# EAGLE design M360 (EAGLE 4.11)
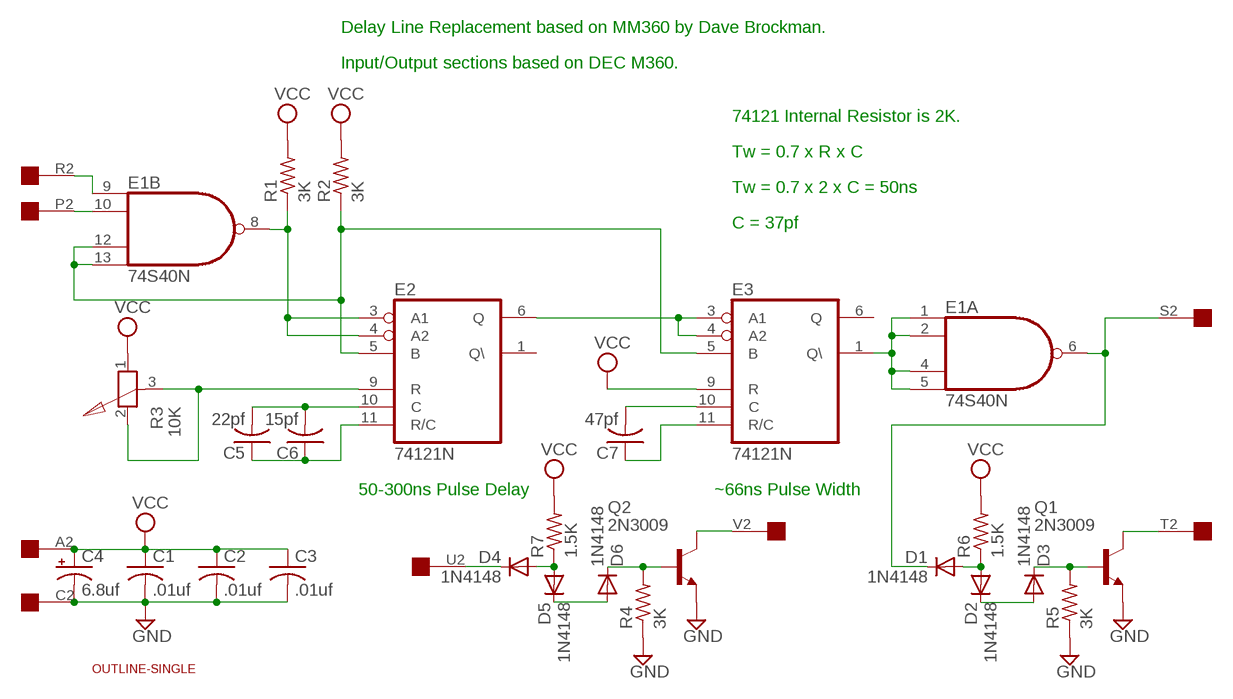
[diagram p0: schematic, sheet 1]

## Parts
C1  .01uf  C-US050-025X075  [C050-025X075]
C2  .01uf  C-US050-025X075  [C050-025X075]
C3  .01uf  C-US050-025X075  [C050-025X075]
C4  6.8uf  CPOL-USE15-5AXIAL  [E15-5]
C5  22pf  C-US050-025X075  [C050-025X075]
C6  15pf  C-US050-025X075  [C050-025X075]
C7  47pf  C-US050-025X075  [C050-025X075]
D1  1N4148  [DO35-10]
D2  1N4148  [DO35-10]
D3  1N4148  [DO35-10]
D4  1N4148  [DO35-10]
D5  1N4148  [DO35-10]
D6  1N4148  [DO35-10]
E1  74S40N  74S20N  [DIL14]
E2  74121N  [DIL14]
E3  74121N  [DIL14]
Q1  2N3009  2N2405  [TO5]
Q2  2N3009  2N2405  [TO5]
R1  3K  R-US_0207/10  [0207/10]
R2  3K  R-US_0207/10  [0207/10]
R3  10K  POT-TRIM  [PT-SPIN]
R4  3K  R-US_0207/10  [0207/10]
R5  3K  R-US_0207/10  [0207/10]
R6  1.5K  R-US_0207/10  [0207/10]
R7  1.5K  R-US_0207/10  [0207/10]
U$1  OUTLINE-SINGLE  [SINGLE]
U$3  EDGE-1  [EDGE-CON1]

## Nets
GND [supply]: C1.2 C2.2 C3.2 C4.- Q1.1(E) Q2.1(E) R4.1 R5.1 U$3.C2
N$1: E2.6(Q) E3.3(A1) E3.4(A2)
N$2: E1.8(B:O) E2.3(A1) E2.4(A2) R1.1
N$3: E1.12(B:I2) E1.13(B:I3) E2.5(B) E3.5(B) R2.1
N$4: E1.1(A:I0) E1.2(A:I1) E1.4(A:I2) E1.5(A:I3) E3.1(Q\)
N$5: E1.10(B:I1) U$3.P2
N$6: E1.9(B:I0) U$3.R2
N$7: C5.2 C6.2 E2.10(C)
N$8: C7.2 E3.10(C)
N$9: C5.1 C6.1 E2.11(R/C)
N$10: E2.9(R) R3.2 R3.3
N$11: D1.C E1.6(A:O) U$3.S2
N$12: Q2.3(C) U$3.V2
N$13: Q1.3(C) U$3.T2
N$14: D4.C U$3.U2
N$15: D6.C Q2.2(B) R4.2
N$16: C7.1 E3.11(R/C)
N$17: D5.C D6.A
N$18: D4.A D5.A R7.1
N$19: D1.A D2.A R6.1
N$20: D2.C D3.A
N$21: D3.C Q1.2(B) R5.2
VCC [supply]: C1.1 C2.1 C3.1 C4.+ E3.9(R) R1.2 R2.2 R3.1 R6.2 R7.2 U$3.A2
Unconnected: E2.1(Q\) E3.6(Q) U$3.B2 U$3.D2 U$3.E2 U$3.F2 U$3.H2 U$3.J2 U$3.K2 U$3.L2 U$3.M2 U$3.N2

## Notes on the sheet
- Delay Line Replacement based on MM360 by Dave Brockman.
- Input/Output sections based on DEC M360.
- 74121 Internal Resistor is 2K.
- Tw = 0.7 x R x C
- Tw = 0.7 x 2 x C = 50ns
- C = 37pf
- 50-300ns Pulse Delay | ~66ns Pulse Width

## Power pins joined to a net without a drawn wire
GND: E1.7(P:GND) E2.7(GND) E3.7(GND)
VCC: E1.14(P:VCC) E2.14(VCC) E3.14(VCC)

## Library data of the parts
C1-C3 C5-C7 = rcl:C-US: CAPACITOR, American symbol
C4 = rcl:CPOL-US: POLARIZED CAPACITOR, American symbol
D1-D6 = diode:1N4148: DIODE
E1 = 74xx-us:74*20: Dual 4-input NAND gate
E2 E3 = 74xx-jameco:74*121: Monostable MULTIVIBRATOR, schmitt trigger inputs
Q1 Q2 = transistor:2N2405: NPN TRANSISTOR
R1 R2 R4-R7 = rcl:R-US_: RESISTOR, American symbol
R3 = discrete:POT-TRIM
U$1 = dec-con:OUTLINE-*: Board outlines for DEC boards.
U$3 = dec-con:EDGE-1: Single-Sided DEC Edge Connector -- (side 2)

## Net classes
1 supply: width 0.762 mm, drill 0.508 mm

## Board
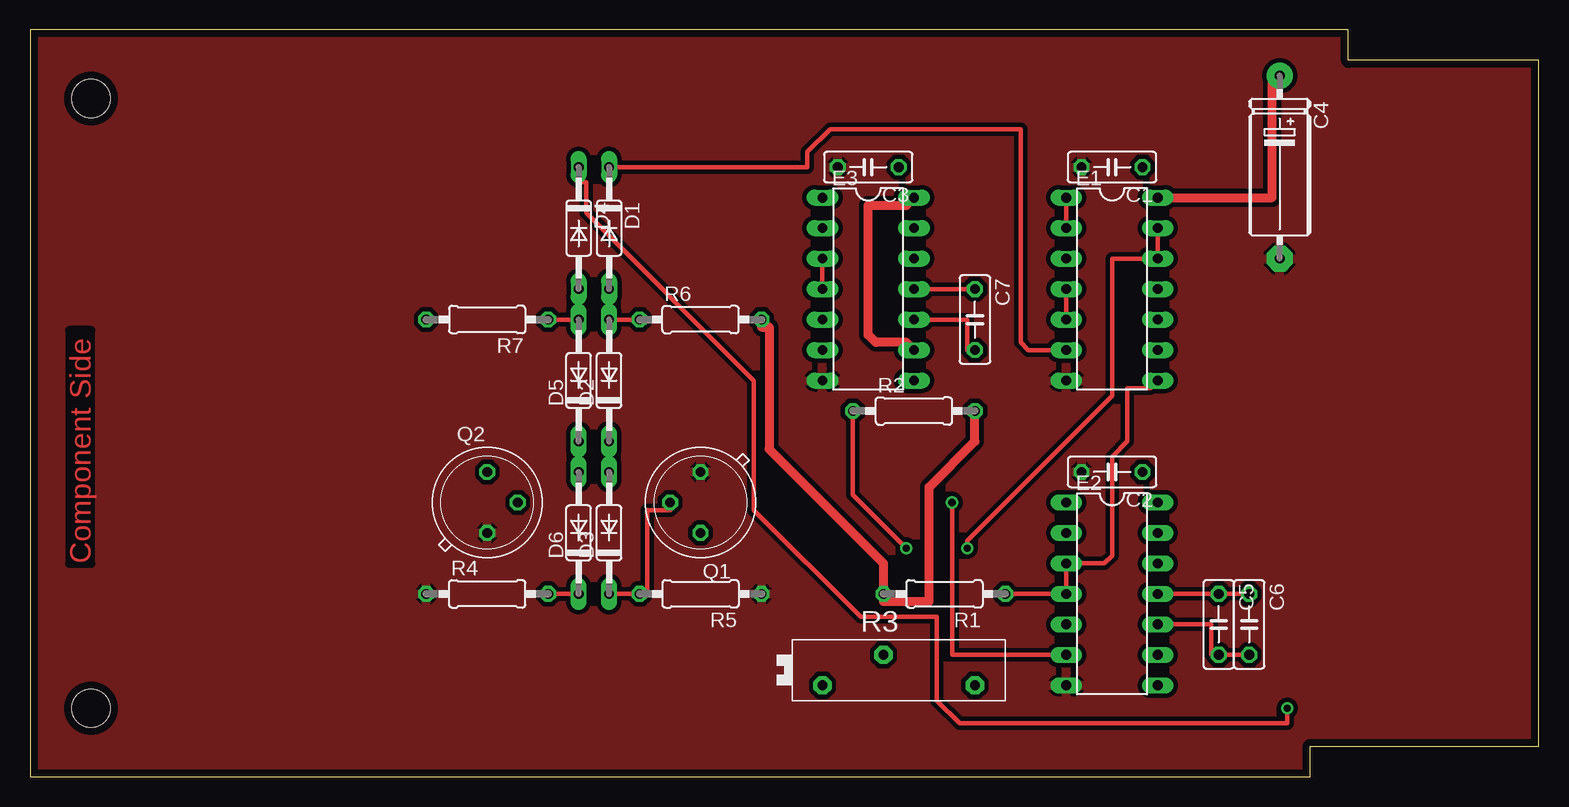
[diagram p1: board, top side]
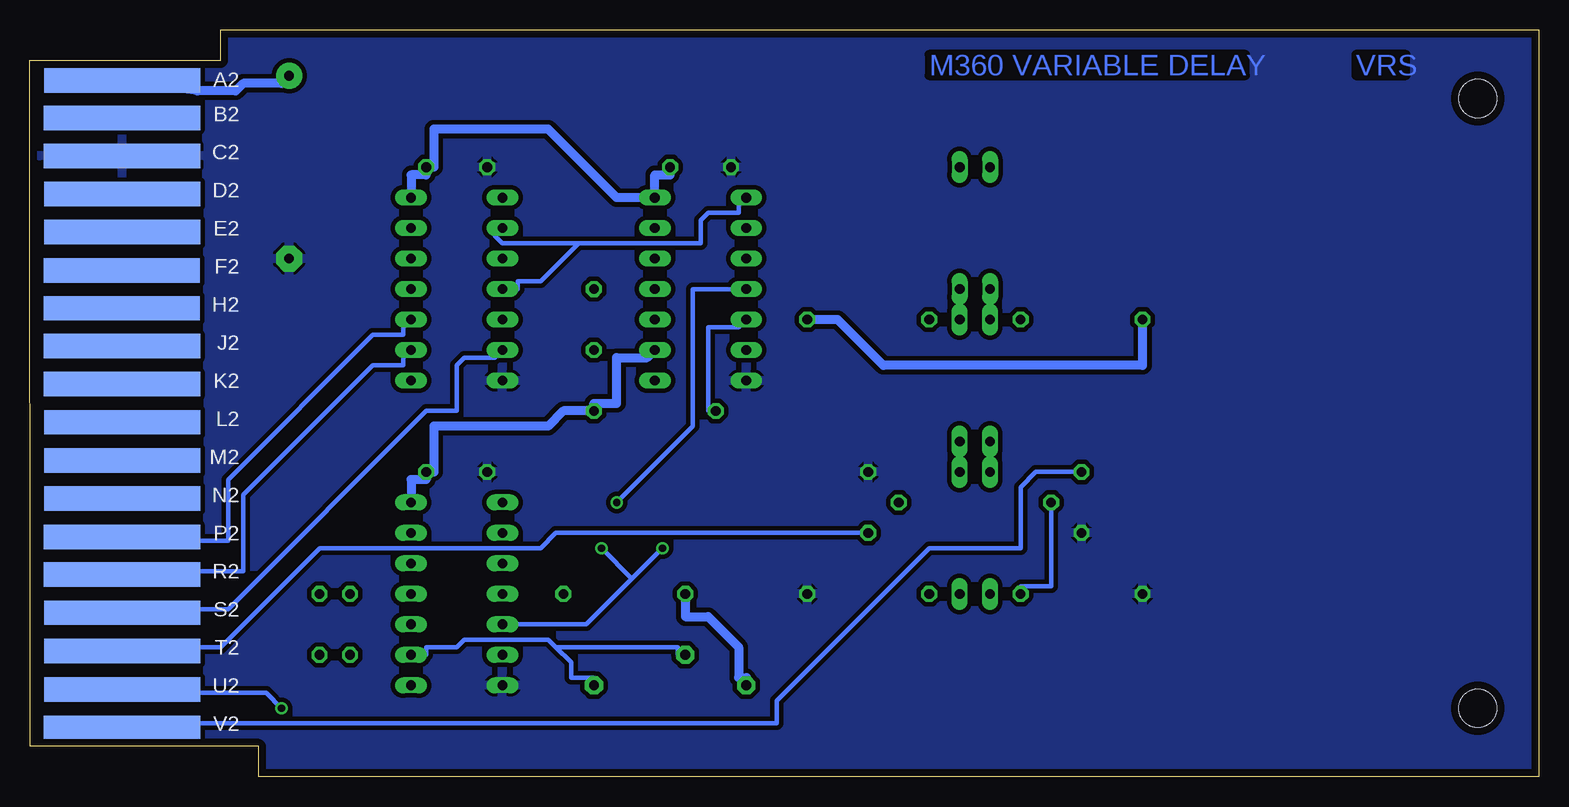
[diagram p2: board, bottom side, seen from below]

Size 125.73 x 62.23 mm. Coordinates in mm from the lower left corner, seen from the top.
Copper layers (1*16): Top 0.035mm / dielectric 1.5mm / Bottom 0.035mm
Design rules "15mils": minimum track width 15mil, minimum drill 24mil, track to track 15mil, track to pad 10mil, pad to pad 10mil, via to via 10mil, smd to smd 10mil, copper to edge 25mil, drill to drill 10mil, minimum pad ring 10mil, minimum via ring 8mil, stop-mask expansion 0mil, vias tented up to drill 0mil, thermal gap 10mil

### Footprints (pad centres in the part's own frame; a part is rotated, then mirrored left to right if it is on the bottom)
C050-025X075 = drill 0.813 octagon: 1 -2.54,0; 2 2.54,0
E15-5 = drill 0.813 pad 2.159 round: + -7.62,0 | drill 0.813 pad 2.159 octagon: - 7.62,0
DO35-10 = drill 0.813 long: A 5.08,0; C -5.08,0
DIL14 = drill 0.813 long: 1 -7.62,-3.81; 2 -5.08,-3.81; 3 -2.54,-3.81; 4 0,-3.81; 5 2.54,-3.81; 6 5.08,-3.81; 7 7.62,-3.81; 8 7.62,3.81; 9 5.08,3.81; 10 2.54,3.81; 11 0,3.81; 12 -2.54,3.81; 13 -5.08,3.81; 14 -7.62,3.81
TO5 = drill 0.813 octagon: 1 0,-2.54; 2 2.54,0; 3 0,2.54
0207/10 = drill 0.813 octagon: 1 -5.08,0; 2 5.08,0
PT-SPIN = drill 0.813 pad 1.524 octagon: 1 -6.35,-1.27; 2 6.35,-1.27; 3 -1.27,1.27
SINGLE = hole 3.175: 120.65,56.515; 120.65,5.715
EDGE-CON1 = smd 13.017 x 2.032 bottom: A2 7.69,4.194; B2 7.668,7.328; C2 7.668,10.49; D2 7.693,13.665; E2 7.693,16.84; F2 7.642,20.041; H2 7.642,23.19; J2 7.668,26.34; K2 7.668,29.515; L2 7.693,32.69; M2 7.693,35.89; N2 7.693,39.04; P2 7.668,42.24; R2 7.668,45.39; S2 7.693,48.565; T2 7.693,51.74; U2 7.693,54.966 | smd 13.017 x 1.905 bottom: V2 7.668,58.102

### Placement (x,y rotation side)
C1  90.17,50.8 180 top
C2  90.17,25.4 180 top
C3  69.85,50.8 180 top
C4  104.14,50.8 270 top
C5  99.06,12.7 270 top
C6  101.6,12.7 270 top
C7  78.74,38.1 270 top
D1  48.26,45.72 270 top
D2  48.26,33.02 90 top
D3  48.26,20.32 90 top
D4  45.72,45.72 270 top
D5  45.72,33.02 90 top
D6  45.72,20.32 90 top
E1  90.17,40.64 270 top
E2  90.17,15.24 270 top
E3  69.85,40.64 270 top
Q1  55.88,22.86 180 top
Q2  38.1,22.86 0 top
R1  76.2,15.24 180 top
R2  73.66,30.48 0 top
R3  72.39,8.89 0 top
R4  38.1,15.24 0 top
R5  55.88,15.24 180 top
R6  55.88,38.1 0 top
R7  38.1,38.1 180 top
U$1  125.73,62.23 180 top
U$3  125.73,62.23 180 top

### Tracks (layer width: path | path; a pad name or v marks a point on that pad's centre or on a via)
GND
  pour Bottom: 0,0 125.73,0 125.73,62.23 0,62.23
  pour Top: 0,0 125.73,0 125.73,62.23 0,62.23
N$1  (via drill 0.61)
  Top 0.381: E3.4 E3.3 | v76.83,22.86 76.83,10.16 E2.6
  Bottom 0.381: v76.83,22.86 70.48,29.21 70.48,40.64 E3.4
N$2
  Top 0.381: R1.1 E2.4 E2.3 89.53,17.78 90.17,18.41 90.17,26.67 91.44,27.94 91.44,32.38 93.34,32.38 E1.8
N$3  (via drill 0.61)
  Top 0.381: E1.13 E1.12 90.17,43.18 90.17,31.75 78.11,19.68 v78.11,19.05 | v73.03,19.05 68.58,23.5 R2.1
  Bottom 0.381: R2.1 69.22,30.48 69.22,37.47 66.67,37.47 E3.5 | v73.03,19.05 75.56,16.51 | 75.56,16.51 79.38,12.7 E2.5 | 75.56,16.51 v78.11,19.05
N$4
  Top 0.381: E1.4 E1.5 | E1.2 E1.1
  Bottom 0.381: 80.01,44.45 86.36,44.45 87,45.09 E1.2 | 80.01,44.45 69.85,44.45 69.85,46.35 69.22,46.99 66.67,46.99 66.67,47.62 E3.1 | 80.01,44.45 83.19,41.27 85.09,41.27 85.09,40.64 E1.4
N$5
  Bottom 0.381: E1.10 94.61,37.47 94.61,36.83 97.16,36.83 109.22,24.77 109.22,19.68 111.76,19.68 U$3.P2
N$6
  Bottom 0.381: E1.9 94.61,34.92 94.61,34.29 97.16,34.29 107.95,23.5 107.95,17.14 111.76,17.14 U$3.R2
N$7
  Top 0.381: E2.10 98.42,12.7 98.42,10.16 C5.2 C6.2
N$8
  Top 0.381: E3.10 78.11,38.1 78.11,35.56 C7.2
N$9
  Top 0.381: E2.11 C5.1 C6.1
N$10
  Bottom 0.381: 81.92,10.79 80.64,9.53 80.64,8.26 78.74,8.26 R3.2 | 81.92,10.79 82.55,11.43 89.53,11.43 90.17,10.79 92.71,10.79 92.71,10.16 E2.9 | 81.92,10.79 71.75,10.79 71.75,10.16 R3.3
N$11
  Top 0.381: D1.C 64.77,50.8 64.77,52.07 66.67,53.98 82.55,53.98 82.55,36.2 83.19,35.56 E1.6
  Bottom 0.381: E1.6 87,34.92 89.53,34.92 90.17,34.29 90.17,30.48 92.71,30.48 109.22,13.97 111.76,13.97 U$3.S2
N$12
  Bottom 0.381: Q2.3 41.91,25.4 43.18,24.13 43.18,19.05 50.8,19.05 63.5,6.35 63.5,4.45 111.76,4.45 U$3.V2
N$13
  Bottom 0.381: Q1.3 81.92,20.32 83.19,19.05 101.6,19.05 109.86,10.79 111.76,10.79 U$3.T2
N$14  (via drill 0.61)
  Top 0.381: v104.78,5.71 104.78,4.45 77.47,4.45 75.56,6.35 75.56,13.34 69.22,13.34 60.33,22.23 60.33,33.02 46.35,46.99 46.35,49.53 45.72,49.53 D4.C
  Bottom 0.381: v104.78,5.71 106.05,6.99 111.76,6.99 U$3.U2
N$15
  Top 0.381: R4.2 D6.C
  Bottom 0.381: Q2.2 40.64,15.88 43.18,15.88 R4.2
N$16
  Top 0.381: E3.11 C7.1
N$17
  Top 0.381: D6.A D5.C
N$18
  Top 0.381: R7.1 D5.A D4.A
N$19
  Top 0.381: D1.A D2.A R6.1
N$20
  Top 0.381: D3.A D2.C
N$21
  Top 0.381: D3.C R5.2 51.44,15.24 51.44,22.23 53.34,22.23 Q1.2
VCC
  Top 0.762: E1.14 103.5,48.26 103.5,57.78 C4.+ | E3.14 73.03,47.62 69.85,47.62 69.85,36.83 70.48,36.2 73.03,36.2 E3.9 | R2.2 78.74,27.94 74.93,24.13 74.93,14.61 71.12,14.61 R1.2 71.12,17.78 61.59,27.3 61.59,37.47 60.96,37.47 R6.2
  Bottom 0.762: E1.14 93.98,50.16 92.71,50.16 C1.1 92.08,50.8 92.08,53.98 82.55,53.98 76.83,48.26 E3.14 73.66,50.16 72.39,50.16 C3.1 | C4.+ 104.78,57.78 107.95,57.78 108.58,57.15 111.76,57.15 U$3.A2 | R7.2 33.02,34.29 54.61,34.29 58.42,38.1 R6.2 | R1.2 71.12,13.34 69.22,13.34 66.67,10.79 66.67,8.26 66.04,8.26 R3.1 | E2.14 93.98,24.77 92.71,24.77 C2.1 92.08,25.4 92.08,29.21 82.55,29.21 81.28,30.48 R2.2 78.74,31.11 76.83,31.11 76.83,34.92 74.3,34.92 E3.9

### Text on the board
Top: Component Side
Bottom: VRS | M360 VARIABLE DELAY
